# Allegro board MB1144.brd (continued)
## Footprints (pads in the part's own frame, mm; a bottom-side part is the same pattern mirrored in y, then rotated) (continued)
XTAL_SOCKET
  round 2.108 hole 1.346: 1(0,0) 2(-5.08,0)

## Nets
+1V8: C107.1 C109.1 C120.1 C123.1 TP16.1 U27.2 U27.4 U29.D1 U29.D8 U29.G9
+3V3: C61.2 C69.2 C70.2 C71.1 C78.2 C84.1 C85.1 C98.1 C101.1 C111.1 C126.1 CN2.28 CN13.7 CN19.24 CN19.25 JP1.3 JP2.1 JP10.3 LD1.1 LD2.1 LD3.1 LD4.1 R6.1 R8.1 R9.1 R14.2 R20.2 R44.1 R70.1 R112.1 R115.1 R204.1 R211.1 R212.1 R214.1 R215.1 R216.1 R217.1 R219.1 R242.1 TP17.1 U10.22 U10.26 U11.7 U12.8 U21.7 U21.18 U22.7 U22.18 U27.3 U28.4 U29.B2 U29.C2 U29.E9
+3V3_STLINK: C81.1 C86.2 C87.1 C93.2 C94.2 C95.2 C96.1 CN16.4 JP18.1 R181.2 R252.2 T4.3 U20.5 U23.1 U23.9 U23.24 U23.36 U23.48 U24.1 U25.8
+3V6: C20.1 C99.1 R207.2 TP12.1 U5.G5 U26.2 U26.4
+5V: C75.1 C116.1 C135.1 C138.1 C140.1 CN2.25 JP17.1 JP17.3 JP17.5 JP17.7 R128.1 R165.2 R169.2 R223.1 SB43.2 TP10.1 U1.5 U15.4 U26.3 U28.6 U30.6 U34.6
D5V: CN6.28 D7.1 JP17.2
GND: B1.1 B1.4 BT1.2 C1.1 C2.1 C3.2 C4.1 C5.1 C6.1 C7.1 C8.2 C9.1 C10.1 C11.2 C12.2 C13.1 C14.1 C15.2 C16.1 C17.2 C18.2 C19.2 C20.2 C21.2 C22.2 C23.1 C24.1 C25.1 C26.1 C27.2 C28.2 C29.2 C30.2 C31.2 C32.2 C33.2 C34.1 C35.1 C36.1 C37.1 C38.1 C39.1 C40.2 C41.1 C42.2 C43.1 C44.2 C45.2 C46.2 C47.1 C48.1 C49.1 C50.1 C51.1 C52.1 C53.2 C54.2 C55.2 C56.2 C57.2 C58.1 C59.2 C60.1 C61.1 C63.2 C65.2 C66.1 C67.2 C68.1 C69.1 C70.1 C71.2 C72.2 C73.2 C74.1 C75.2 C76.2 C78.1 C79.2 C80.2 C81.2 C82.2 C83.2 C84.2 C85.2 C86.1 C87.2 C88.1 C89.1 C90.2 C91.1 C92.2 C93.1 C94.1 C95.1 C96.2 C97.2 C98.2 C99.2 C100.2 C101.2 C103.2 C104.2 C107.2 C108.2 C109.2 C110.2 C111.2 C112.2 C114.2 C116.2 C117.1 C118.2 C119.2 C120.2 C121.2 C122.2 C123.2 C125.1 C126.2 C127.1 C128.1 C131.2 C132.2 C133.2 C134.2 C135.2 C137.2 C138.2 C139.2 C140.2 C141.1 C142.2 C143.1 C144.2 C145.2 CN1.5 CN1.6 CN1.7 CN1.8 CN1.9 CN1.10 CN2.2 CN2.4 CN2.6 CN2.8 CN2.10 CN2.12 CN2.16 CN2.18 CN2.20 CN2.22 CN3.7 CN4.3 CN5.3 CN5.6 CN5.10 CN5.11 CN6.1 CN6.11 CN6.22 CN6.36 CN6.39 CN7.1 CN7.15 CN7.26 CN7.39 CN8.1 CN9.5 CN9.10 CN9.11 CN12.3 CN12.5 CN12.9 CN12.11 CN12.13 CN12.15 CN12.17 CN12.19 CN13.8 CN15.4 CN15.6 CN15.8 CN15.10 CN15.12 CN15.14 CN15.16 CN15.18 CN15.20 CN16.2 CN17.4 CN17.5 CN17.6 CN18.6 CN18.9 CN19.26 CN19.27 CN19.30 CN23.5 CN23.17 D1.D2 D2.3 JP4.1 JP13.1 L2.4 L2.5 L2.6 L3.2 LD7.2 LD8.1 R19.2 R21.1 R27.2 R30.1 R45.2 R52.1 R77.1 R100.2 R101.2 R102.2 R113.2 R121.1 R124.2 R137.2 R138.2 R139.2 R155.1 R159.1 R163.1 R164.1 R168.2 R170.1 R171.2 R172.1 R174.1 R183.2 R184.2 R187.2 R191.2 R192.1 R195.2 R196.2 R202.1 R203.2 R206.2 R209.1 R213.2 R218.2 R220.2 R221.2 R224.1 R226.1 R230.1 R232.1 R234.1 R239.2 R240.2 R241.2 R243.1 R245.2 R251.1 R261.1 R267.2 RV1.2 RV1.3 RV3.3 SB7.2 SW1.3 T1.2 T6.2 TP1.1 TP3.1 TP11.1 TP18.1 U1.2 U2.D1 U2.E6 U3.7 U3.12 U3.13 U3.17 U4.7 U4.12 U4.13 U4.17 U5.E8 U5.H2 U5.H7 U6.1 U6.2 U6.3 U6.4 U7.16 U7.30 U7.31 U7.38 U7.51 U7.61 U7.71 U7.83 U7.94 U7.107 U7.120 U7.130 U7.143 U8.2 U9.4 U10.4 U10.12 U10.23 U10.25 U11.8 U12.4 U13.3 U14.8 U15.11 U16.3 U17.2 U18.2 U19.2 U20.2 U21.4 U21.10 U21.15 U21.21 U21.28 U21.34 U21.39 U21.45 U21.48 U22.4 U22.10 U22.15 U22.21 U22.28 U22.34 U22.39 U22.45 U23.8 U23.23 U23.35 U23.47 U24.4 U24.5 U25.4 U27.1 U28.2 U28.7 U29.A1 U29.A3 U29.A4 U29.A5 U29.C1 U29.D6 U29.E2 U29.E7 U29.E8 U29.F7 U29.G5 U29.H9 U30.2 U30.4 U30.14 U30.22 U32.3 U32.10 U33.9 U33.25 U34.2 U34.7 U35.5 U36.2 U36.5 U37.4
VDD: B2.1 B2.4 C12.1 C18.1 C19.1 C21.1 C22.1 C31.1 C39.2 C40.1 C44.1 C49.2 C66.2 C72.1 C74.2 C76.1 C79.1 C83.1 C90.1 C92.1 C97.1 C112.1 C118.1 C119.1 C121.1 C132.1 C134.1 CN3.5 CN7.40 CN12.1 CN15.1 CN15.2 CN18.4 JP2.2 JP11.1 JP12.1 JP16.3 R22.1 R25.1 R28.1 R29.1 R32.1 R41.1 R42.1 R46.2 R51.2 R57.2 R60.2 R74.1 R96.2 R114.2 R117.2 R120.2 R126.2 R127.1 R133.1 R135.2 R152.2 R153.2 R157.2 R160.2 R161.1 R166.1 R175.1 R176.1 R178.1 R182.1 R185.1 R186.1 R190.1 R193.1 R197.1 R200.2 R229.1 R231.1 R233.1 R237.1 R246.1 R247.2 R248.2 R249.2 R250.2 R263.1 R264.1 RV3.1 SW1.1 T3.4 TP5.1 U2.A6 U2.D6 U2.E1 U3.1 U4.1 U5.D8 U5.F1 U6.8 U8.3 U9.8 U12.1 U12.5 U13.5 U14.16 U15.5 U16.5 U21.1 U21.24 U21.25 U21.31 U21.42 U22.31 U22.42 U24.8 U25.1 U25.5 U29.D2 U30.21 U32.6 U32.14 U33.21
VDD_ADJ: C131.1 C133.1 JP2.3 R236.1 TP13.1 U34.4
VDD_IO: C35.2 C46.1 JP3.2 TP4.1 U7.95 U7.131
VDD_MCU: C32.1 C38.2 C41.2 C42.1 C43.2 C45.1 C48.2 C50.2 C51.2 JP1.1 JP3.1 JP10.1 JP11.2 JP11.3 U7.17 U7.39 U7.52 U7.62 U7.72 U7.84 U7.108 U7.121 U7.144
VDD_USB: C33.1 C36.2 JP1.2 TP2.1 U7.106
VDDA: C59.1 C60.2 CN10.2 L1.2 TP8.1 U7.33
A0: CN6.25 U2.A3 U5.E2 U7.10 U21.47
A0_1DELAY: SB44.1 U21.2 U21.40
A0_2DELAY: SB45.1 U21.9
A1: CN6.26 SB51.1 U2.A4 U5.D2 U7.11 U21.37
A1_1DELAY: SB50.1 U21.12
A1_BUF: R166.2 SB50.2 SB51.2 U22.1 U22.24
A2: CN6.32 U2.A5 U5.C2 U7.12
A3: CN6.34 U2.B3 U5.A2 U7.13
A4: CN6.37 U2.B4 U5.B2 U7.14
A5: CN6.38 U2.C3 U5.D3 U7.15
A6: CN7.17 U2.C4 U5.C3 U7.50
A7: CN7.18 U2.D4 U5.A3 U7.53
A8: CN7.16 U2.H2 U5.B6 U7.54
A9: CN7.14 U2.H3 U5.A6 U7.55
A10: CN7.12 U2.H4 U5.C6 U7.56
A11: CN7.11 U2.H5 U5.D6 U7.57
A12: CN6.13 U2.G3 U5.B7 U7.87
A13: CN6.12 U2.G4 U5.A7 U7.88
A14: CN6.14 U2.F3 U5.C7 U7.89
A15: CN6.10 U2.F4 U5.D7 U7.90
A16: CN14.30 U2.E4 U5.E7
A17: R151.1 U2.D3 U5.B3
A18: CN14.34 U2.H1 U5.C4
A19: R139.1 R150.1 U2.G2 U5.D5
A20: R84.1 R100.1 U2.H6 U5.D4
A21: R85.1 R101.1 U2.E3 U5.C5
A22: R86.1 R102.1 U5.B8
A23: R138.1 R149.1 U5.C8
AIN_1: R183.1 R186.2 U23.10
BL_VDD: C113.2 C115.1 CN19.28 L4.1 R259.1
BOOT0: CN7.20 JP8.1 R67.1 U7.138
COMP2_INP: CN11.44 JP7.3
COMP2_OUT: CN11.14 TP6.1
D0: CN14.36 U2.B6 U5.E3 U22.26
D1: CN14.38 U2.C5 U5.H3 U22.27
D2: CN6.17 U2.C6 U5.E4 U7.114 U22.29
D3: CN6.16 U2.D5 U5.H4 U7.115 U22.30
D4: CN7.10 U2.E5 U5.H5 U7.58 U22.32
D5: CN7.9 U2.F5 U5.E5 U7.59 U22.33
D6: CN7.8 U2.F6 U5.H6 U7.60 U22.35
D7: CN7.7 U2.G6 U5.E6 U7.63 U22.36
D8: CN7.6 U2.B1 U5.F3 U7.64 U22.37
D9: CN7.5 U2.C1 U5.G3 U7.65 U22.38
D10: CN7.4 U2.C2 U5.F4 U7.66 U22.40
D11: CN7.3 U2.D2 U5.G4 U7.67 U22.41
D12: CN7.2 U2.E2 U5.F5 U7.68 U22.43
D13: CN14.24 U2.F2 U5.G6 U22.44
D14: CN14.26 U2.F1 U5.F6 U22.46
D15: CN14.28 U2.G1 U5.G7 U22.47
E5V: C100.1 D5.1 JP17.8 L2.3
I2C_SCL: CN3.3 R60.1 R61.1 U29.H1 U32.4 U33.19
I2C_SDA: CN3.1 R57.1 R58.1 U29.F3 U32.5 U33.20
IRDA_RX: JP15.4 U11.4
LCD_CSN: CN19.1 SB46.2 SB47.2
LCD_D0: CN19.6 U22.23
LCD_D1: CN19.7 U22.22
LCD_D2: CN19.8 U22.20
LCD_D3: CN19.9 U22.19
LCD_D4: CN19.10 U22.17
LCD_D5: CN19.11 U22.16
LCD_D6: CN19.12 U22.14
LCD_D7: CN19.13 U22.13
LCD_D8: CN19.14 U22.12
LCD_D9: CN19.15 U22.11
LCD_D10: CN19.16 U22.9
LCD_D11: CN19.17 U22.8
LCD_D12: CN19.18 U22.6
LCD_D13: CN19.19 U22.5
LCD_D14: CN19.20 U22.3
LCD_D15: CN19.21 U22.2
LCD_NE3_BUF: R161.2 SB48.2 SB49.2 U22.25 U22.48
LCD_RDN: CN19.4 U21.6
LCD_RS: CN19.2 SB44.2 SB45.2
LCD_RSTN: CN19.5 U21.8
LCD_WRN: CN19.3 U21.5
LCDCOM0: CN11.3 U7.100
LCDCOM1: CN11.1 U7.101
LCDCOM2: CN11.5 U7.102
LCDCOM3: CN11.7 U7.140
LCDCOM4: CN14.7 U7.111
LCDCOM5: CN14.5 U7.112
LCDCOM6: CN14.3 U7.113
LCDCOM7: CN14.1 U7.116
LCDSEG0: CN14.47 R82.1
LCDSEG1: CN11.35 R81.1
LCDSEG2: CN11.33 R78.2
LCDSEG3: CN11.41 R68.1
LCDSEG4: CN11.39 R66.1
LCDSEG5: CN11.37 R62.1
LCDSEG6: CN11.47 R56.1
LCDSEG7: CN11.45 RS1.9 U7.133 U24.6
LCDSEG8: CN11.43 RS1.5 U7.134 U23.19
LCDSEG9: CN11.13 U7.135
LCDSEG10: CN11.11 R50.1
LCDSEG11: CN11.9 R48.1
LCDSEG12: CN11.19 R39.2
LCDSEG13: CN11.17 R38.1
LCDSEG14: CN11.15 U7.75
LCDSEG15: CN11.25 U7.76
LCDSEG16: CN11.23 U7.139
LCDSEG17: CN11.21 RS1.7 U7.110 U23.17
LCDSEG18: CN11.31 R97.1
LCDSEG19: CN11.29 R98.1
LCDSEG20: CN11.27 R99.1
LCDSEG21: CN14.9 U7.137
LCDSEG22: CN14.11 R65.1
LCDSEG23: CN14.13 R64.1
LCDSEG24: CN14.15 R36.1
LCDSEG25: CN14.17 R33.1
LCDSEG26: CN14.19 SB28.2 U7.98
LCDSEG27: CN14.21 SB29.2 U7.99
LCDSEG28: CN14.23 U7.77
LCDSEG29: CN14.25 U7.78
LCDSEG30: CN14.27 U7.79
LCDSEG31: CN14.29 U7.80
LCDSEG32: CN14.31 U7.81
LCDSEG33: CN14.33 U7.82
LCDSEG34: CN14.35 U7.85
LCDSEG35: CN14.37 U7.86
LCDSEG36: CN14.39 U7.141
LCDSEG37: CN14.41 U7.142
LCDSEG38: CN14.43 R103.2
LCDSEG39: CN14.45 R104.2
LED_STLINK: R253.1 R254.1 U23.30
MCO: U23.29
MICROAB_N: CN1.2 D1.D1 R3.1
MICROAB_P: CN1.3 D1.C1 R4.1
NE3_1DELAY: SB46.1 SB48.1 U21.3 U21.38
NE3_2DELAY: SB47.1 U21.11
NETB2_2: B2.2 B2.3 R244.1 R245.1
NETB3_1: B3.1 R248.1 U33.3
NETB3_2: B3.2 R246.2 U33.1
NETB3_3: B3.3 R247.1 U33.2
NETB3_4: B3.4 R249.1 U33.4
NETB3_5: B3.5 R251.2
NETB3_6: B3.6 R250.1 U33.5
NETBT1_1: BT1.1 JP12.3
NETC1_2: C1.2 CN2.33 SB32.1
NETC2_2: C2.2 CN2.34 SB31.1
NETC3_1: C3.1 R7.2 SB17.1
NETC4_2: C4.2 CN2.31 SB1.2 SB35.1
NETC5_2: C5.2 CN2.30 R20.1 SB3.1
NETC6_2: C6.2 R12.2 SB20.1
NETC7_2: C7.2 CN2.1 R14.1 SB29.1
NETC8_1: C8.1 SB1.1
NETC9_2: C9.2 CN2.29 SB37.2
NETC10_2: C10.2 R17.1 SB42.1
NETC11_1: C11.1 R13.2 R19.1 SB16.1
NETC13_2: C13.2 R10.1 SB36.1
NETC14_2: C14.2 R11.1 SB34.1
NETC15_1: C15.1 CN1.1 CN11.2 D1.B3 R1.1 R2.2 R108.2 U1.1
NETC16_2: C16.2 R15.1 SB25.2
NETC17_1: C17.1 R16.2 SB22.1
NETC23_2: C23.2 C28.1 U4.2 U4.3 U4.9
NETC24_2: C24.2 C27.1 U3.2 U3.3 U3.9
NETC25_2: C25.2 U4.4
NETC26_2: C26.2 U3.4
NETC29_1: C29.1 CN4.2 R26.2 R27.1 U3.5 U3.8
NETC30_1: C30.1 R28.2 U5.B5
NETC34_2: C34.2 SB4.1
NETC37_2: C37.2 SB6.1
NETC47_2: C47.2 R72.1 R73.2
NETC52_2: C52.2 C53.1 R92.2 U7.32
NETC55_1: C55.1 R95.2 X2.1
NETC56_1: C56.1 R87.1 X1.2
NETC57_1: C57.1 R88.1 X1.1
NETC62_1: C62.1 U10.24
NETC62_2: C62.2 U10.28
NETC63_1: C63.1 U10.3
NETC64_1: C64.1 U10.1
NETC64_2: C64.2 U10.2
NETC65_1: C65.1 U10.27
NETC67_1: C67.1 C68.2 R115.2 U11.6
NETC73_1: C73.1 R69.2 R122.2
NETC77_1: C77.1 U14.9
NETC77_2: C77.2 R130.2 R134.2
NETC80_1: C80.1 D5.2 D6.2 D7.2 D8.2 U20.1 U20.3
NETC82_1: C82.1 U20.4
NETC102_1: C102.1 U29.H8
NETC102_2: C102.2 U29.G8
NETC103_1: C103.1 U29.G7
NETC104_1: C104.1 U29.H7
NETC105_1: C105.1 CN20.4 U29.G6
NETC105_2: C105.2 R195.1
NETC106_1: C106.1 CN20.6 U29.H6
NETC106_2: C106.2 R196.1
NETC108_1: C108.1 U29.E6
NETC110_1: C110.1 U29.F1
NETC113_1: C113.1 C115.2 CN19.22 L3.1
NETC114_1: C114.1 R207.1 R209.2 U26.1
NETC117_2: C117.2 CN23.1 U30.17
NETC122_1: C122.1 U29.D9
NETC124_1: C124.1 L2.1 U31.3 Z1.2
NETC124_2: C124.2 CN22.2 CN22.3 L2.2 U31.2 Z1.1
NETC125_2: C125.2 U29.C9
NETC127_2: C127.2 JP16.1 U29.A7
NETC128_2: C128.2 U29.B6
NETC129_1: C129.1 R226.2 R227.2
NETC129_2: C129.2 U29.B3
NETC130_1: C130.1 R224.2 R225.1
NETC130_2: C130.2 U29.A2
NETC136_1: C136.1 U30.7
NETC136_2: C136.2 U30.5
NETC137_1: C137.1 U30.8
NETC139_1: C139.1 C142.1 JP16.2 R238.2 U35.1 U36.1
NETC144_1: C144.1 R124.1 R128.2 U15.3
NETCN1_4: CN1.4 D1.A3 R5.1
NETCN2_3: CN2.3 SB27.1
NETCN2_5: CN2.5 SB19.1
NETCN2_7: CN2.7 SB30.1
NETCN2_9: CN2.9 SB15.1
NETCN2_11: CN2.11 SB28.1
NETCN2_13: CN2.13 SB13.1
NETCN2_14: CN2.14 R13.1
NETCN2_15: CN2.15 R11.2
NETCN2_17: CN2.17 R10.2
NETCN2_19: CN2.19 R17.2
NETCN2_21: CN2.21 SB5.2
NETCN2_23: CN2.23 SB11.1
NETCN2_24: CN2.24 R7.1
NETCN2_26: CN2.26 R16.1
NETCN2_27: CN2.27 R15.2
NETCN2_32: CN2.32 R12.1
NETCN3_4: CN3.4 U33.12
NETCN3_8: CN3.8 SB43.1
NETCN4_1: CN4.1 R26.1 U3.6
NETCN5_2: CN5.2 D2.2 JP6.2 U8.6
NETCN5_5: CN5.5 R77.2
NETCN5_7: CN5.7 D2.1 R55.1 U8.7
NETCN5_9: CN5.9 R70.2
NETCN6_2: CN6.2 R44.2
NETCN6_30: CN6.30 R80.1
NETCN7_24: CN7.24 SB33.2
NETCN7_25: CN7.25 SB41.2
NETCN7_32: CN7.32 R79.2
NETCN7_33: CN7.33 SB23.2
NETCN7_34: CN7.34 SB24.2
NETCN8_2: CN8.2 R72.2
NETCN9_2: CN9.2 U10.6
NETCN9_3: CN9.3 U10.10
NETCN9_6: CN9.6 U10.5
NETCN9_7: CN9.7 U10.9
NETCN9_8: CN9.8 U10.7
NETCN10_1: CN10.1 R92.1
NETCN11_4: CN11.4 R194.1
NETCN11_6: CN11.6 R5.2
NETCN11_8: CN11.8 R75.2
NETCN11_10: CN11.10 R265.2
NETCN11_12: CN11.12 R266.2
NETCN11_16: CN11.16 CN13.4
NETCN11_18: CN11.18 CN13.6 R108.1
NETCN11_20: CN11.20 CN23.6 R109.1
NETCN11_24: CN11.24 R76.1
NETCN11_26: CN11.26 CN13.5
NETCN11_28: CN11.28 JP14.3 U3.10 U3.11 U3.14 U4.10 U4.11 U4.14
NETCN11_30: CN11.30 R256.1
NETCN11_32: CN11.32 U29.A9 U35.4 U36.4
NETCN11_34: CN11.34 R111.2
NETCN11_38: CN11.38 R107.2
NETCN12_2: CN12.2 CN15.7 R153.1 RS1.14 U17.1
NETCN12_4: CN12.4 CN15.9 R155.2 RS1.12 U17.3
NETCN12_6: CN12.6 CN15.13 R160.1 R162.2 RS1.10 U17.4
NETCN12_8: CN12.8 CN15.5 R152.1 RS1.8 U17.5
NETCN12_10: CN12.10 CN15.15 RS1.4 U18.3
NETCN12_12: CN12.12 SB26.2 U18.4
NETCN12_14: CN12.14 R154.1 R162.1 U19.5
NETCN12_16: CN12.16 R131.1 R156.1 U19.4
NETCN12_18: CN12.18 SB38.2 U19.3
NETCN12_20: CN12.20 SB39.2 U19.1
NETCN13_1: CN13.1 JP15.6
NETCN13_2: CN13.2 U10.13 U11.3 U12.7
NETCN14_2: CN14.2 CN18.3 R178.2
NETCN14_4: CN14.4 R140.2
NETCN14_6: CN14.6 R141.2
NETCN14_8: CN14.8 R142.2
NETCN14_10: CN14.10 JP15.1 JP15.3 JP15.5 R158.1
NETCN14_12: CN14.12 R143.2
NETCN14_14: CN14.14 R144.2
NETCN14_16: CN14.16 R145.2
NETCN14_18: CN14.18 R146.2
NETCN14_20: CN14.20 R147.2
NETCN14_22: CN14.22 R148.2
NETCN14_32: CN14.32 R151.2
NETCN14_40: CN14.40 U2.A1
NETCN14_42: CN14.42 U2.B2
NETCN14_44: CN14.44 R149.2
NETCN14_46: CN14.46 R150.2
NETCN15_3: CN15.3 R126.1 R131.2 RS1.6 U18.1
NETCN15_11: CN15.11 R157.1 R159.2
NETCN15_17: CN15.17 R163.2
NETCN15_19: CN15.19 R164.2
NETCN17_2: CN17.2 R180.2
NETCN17_3: CN17.3 R177.2 R179.2
NETCN18_1: CN18.1 R142.1 R175.2
NETCN18_2: CN18.2 R141.1 R176.2
NETCN18_5: CN18.5 R140.1
NETCN18_7: CN18.7 R147.1 R182.2
NETCN18_8: CN18.8 R148.1 R185.2
NETCN18_10: CN18.10 R194.2
NETCN19_23: CN19.23 R259.2 T6.3
NETCN19_31: CN19.31 U32.16
NETCN19_32: CN19.32 U32.13
NETCN19_33: CN19.33 U32.1
NETCN19_34: CN19.34 U32.15
NETCN20_2: CN20.2 R192.2
NETCN20_3: CN20.3 R191.1
NETCN21_2: CN21.2 R221.1
NETCN21_3: CN21.3 R220.1
NETCN21_4: CN21.4 R227.1
NETCN21_6: CN21.6 R225.2
NETCN22_1: CN22.1 U31.1
NETCN23_2: CN23.2 U30.16
NETCN23_3: CN23.3 U30.15
NETCN23_4: CN23.4 U30.13
NETCN23_7: CN23.7 U30.11
NETCN23_8: CN23.8 U30.12
NETCN23_18: CN23.18 R242.2 U30.9
NETD3_1: D3.1 R59.1
NETD3_2: D3.2 JP8.2
NETD4_1: D4.1 JP9.2
NETD4_2: D4.2 R93.1 U10.16
NETJP4_2: JP4.2 R45.1 U8.8
NETJP4_3: JP4.3 R46.1
NETJP5_1: JP5.1 RV3.2
NETJP5_2: JP5.2 JP7.2
NETJP5_3: JP5.3 R51.1 R52.2
NETJP6_1: JP6.1 R55.2
NETJP7_1: JP7.1 R63.1
NETJP10_2: JP10.2 L1.1
NETJP11_4: JP11.4 R123.1 T2.1 T2.2 T2.5 T2.6 U15.12
NETJP12_2: JP12.2 U7.6
NETJP13_2: JP13.2 R133.2 U5.B4
NETJP14_1: JP14.1 U29.C6
NETJP14_2: JP14.2 U35.3 U36.3
NETJP15_2: JP15.2 U10.17
NETJP19_1: JP19.1 R145.1
NETJP19_2: JP19.2 R21.2 U1.4
NETL4_2: L4.2 R219.2 R223.2
NETLD1_2: LD1.2 R258.2
NETLD2_2: LD2.2 R257.2
NETLD3_2: LD3.2 R256.2
NETLD4_2: LD4.2 R255.2
NETLD5_1: LD5.1 R6.2
NETLD5_2: LD5.2 T1.3
NETLD6_1: LD6.1 R9.2
NETLD6_2: LD6.2 R8.2 R109.2 U1.3
NETLD7_1: LD7.1 R165.1
NETLD8_2: LD8.2 R253.2
NETLD8_3: LD8.3 R254.2
NETLD8_4: LD8.4 R252.1
NETLD9_1: LD9.1 R268.2
NETLD9_2: LD9.2 R110.2 U37.8
NETR1_2: R1.2 R261.2 T1.1
NETR18_1: R18.1 R22.2 U2.B5
NETR23_2: R23.2 U3.15
NETR24_1: R24.1 R146.1
NETR24_2: R24.2 U4.15
NETR25_2: R25.2 U5.F7
NETR29_2: R29.2 R31.1 U4.6
NETR30_2: R30.2 R31.2 U4.5 U4.8
NETR32_2: R32.2 SB10.2 U5.A4
NETR33_2: R33.2 SB4.2 SB30.2 U7.97
NETR34_1: R34.1 R119.2 R189.1
NETR35_1: R35.1 R199.2
NETR36_2: R36.2 SB2.2 SB27.2 U7.96
NETR37_1: R37.1 SB2.1
NETR38_2: R38.2 SB6.2 U7.74
NETR39_1: R39.1 R40.1 SB3.2 U7.73
NETR40_2: R40.2 TS1.1
NETR41_2: R41.2 R43.1 U5.F2
NETR42_2: R42.2 SB7.1 U6.7
NETR48_2: R48.2 SB8.2 U7.70
NETR50_2: R50.2 SB9.2 U7.69
NETR53_2: R53.2 R205.2
NETR54_2: R54.2 R258.1
NETR56_2: R56.2 SB12.2 SB13.2 U7.47
NETR59_2: R59.2 U10.20
NETR62_2: R62.2 SB14.2 SB15.2 U7.46
NETR64_2: R64.2 SB16.2 U7.45
NETR65_2: R65.2 SB17.2 U7.44
NETR66_2: R66.2 SB18.2 SB19.2 U7.43
NETR67_2: R67.2 SW1.2
NETR68_2: R68.2 SB20.2 SB21.2 U7.42
NETR71_1: R71.1 R74.2 U9.1
NETR71_2: R71.2 SB8.1
NETR75_1: R75.1 U8.1
NETR76_2: R76.2 U8.4
NETR78_1: R78.1 SB22.2 U7.37
NETR81_2: R81.2 SB31.2 U7.36
NETR82_2: R82.2 SB32.2 U7.35
NETR89_1: R89.1 R201.2
NETR90_1: R90.1 R208.2
NETR91_1: R91.1 R127.2 U14.12
NETR97_2: R97.2 SB34.2 U7.26
NETR98_2: R98.2 SB36.2 U7.27
NETR99_2: R99.2 SB42.2 U7.28
NETR103_1: R103.1 SB26.1 U7.1
NETR104_1: R104.1 R154.2 U7.2
NETR105_1: R105.1 R198.2
NETR106_1: R106.1 R222.1
NETR107_1: R107.1 U30.24
NETR112_2: R112.2 U11.1
NETR113_1: R113.1 U11.5
NETR114_1: R114.1 R116.1 U12.3
NETR117_1: R117.1 R118.1 R119.1 U12.2
NETR122_1: R122.1 U13.2
NETR123_2: R123.2 R135.1 T2.4
NETR125_1: R125.1 U15.13 U15.14
NETR125_2: R125.2 R132.1 U15.9
NETR129_1: R129.1 R136.2 U15.10
NETR129_2: R129.2 U15.1 U15.2
NETR130_1: R130.1 U14.11
NETR132_2: R132.2 U13.1 U15.8
NETR134_1: R134.1 U14.10
NETR136_1: R136.1 U15.6 U15.7
NETR137_1: R137.1 R144.1 T3.1 T3.2 T3.5 T3.6
NETR143_1: R143.1 R210.2
NETR156_2: R156.2 SB40.2
NETR167_2: R167.2 R171.1 R173.2 T4.1
NETR168_1: R168.1 U23.44
NETR172_2: R172.2 U23.2
NETR174_2: R174.2 U23.3
NETR177_1: R177.1 T4.2
NETR184_1: R184.1 U37.5
NETR187_1: R187.1 U23.20
NETR188_1: R188.1 U23.12
NETR189_2: R189.2 R190.2 U25.2
NETR193_2: R193.2 U25.3
NETR197_2: R197.2 U29.G2
NETR198_1: R198.1 U29.E4
NETR199_1: R199.1 U29.G3
NETR200_1: R200.1 U29.D4 U29.D5
NETR201_1: R201.1 U29.G1
NETR202_2: R202.2 U28.3
NETR203_1: R203.1 R204.2 U28.5
NETR205_1: R205.1 U29.F2
NETR206_1: R206.1 U28.1
NETR208_1: R208.1 U29.E3
NETR210_1: R210.1 U30.26
NETR211_2: R211.2 TP14.1 U30.28
NETR212_2: R212.2 TP15.1 U30.27
NETR213_1: R213.1 U30.23 U33.10
NETR214_2: R214.2 U30.20 U33.6
NETR215_2: R215.2 U30.19 U33.7
NETR216_2: R216.2 U30.1
NETR217_2: R217.2 R218.1 U30.18
NETR222_2: R222.2 U29.D3
NETR228_2: R228.2 R229.2 U32.2 U33.22
NETR230_2: R230.2 R231.2 U33.18
NETR232_2: R232.2 R233.2 U33.23
NETR234_2: R234.2 U34.3
NETR235_1: R235.1 R236.2 U34.5
NETR235_2: R235.2 RV1.1
NETR237_2: R237.2 R243.2 U33.24
NETR238_1: R238.1 U35.2
NETR239_1: R239.1 U32.9
NETR240_1: R240.1 U34.1
NETR241_1: R241.1 U30.3 U33.8
NETR255_1: R255.1 U32.11
NETR257_1: R257.1 U32.8
NETR260_1: R260.1 U33.11
NETR260_2: R260.2 R267.1 T6.1
NETR263_2: R263.2 R265.1 U6.5
NETR264_2: R264.2 R266.1 U6.6
NETSB9_1: SB9.1 U9.6
NETSB12_1: SB12.1 U9.5
NETSB14_1: SB14.1 U9.2
NETSB18_1: SB18.1 U9.3
NETSB21_1: SB21.1 U9.7
NETT3_3: T3.3 U13.4 U16.4
NETTP19_1: TP19.1 U23.21
NETU14_3: U14.3 U16.2
NETU23_13: U23.13 U25.7
OPAMP1_INM: CN14.48 R120.1 R121.2 RV2.1
OPAMP1_INP: R63.2 R83.2
OPAMP1_OUT: R111.1 RV2.2 RV2.3 TP9.1
OSC_IN: C88.2 U23.5 X3.2
OSC_OUT: C89.2 U23.6 X3.1
PA0: CN7.37 R83.1 SB35.2 U7.34
PA4: CN7.38 R73.1 U7.40
PA5: CN7.35 R69.1 U7.41
PA11: CN6.6 D1.D3 R3.2 U7.103
PA12: CN6.7 D1.C3 R4.2 U7.104
PA13: CN6.5 RS1.13 U7.105 U23.27 U24.7
PA14: CN6.8 RS1.11 U7.109 U23.15 U23.26
PB2: CN7.13 R54.1 SB11.2 U7.48
PB6: CN6.40 R118.2 U7.136
PC3: CN7.36 R94.1 U7.29
PC13: R80.2 R244.2 U7.7
PC14: R87.2 SB41.1 U7.8
PC15: R88.2 SB33.1 U7.9
PD3: CN6.15 R23.1 U7.117
PD4: CN6.18 U2.A2 U5.G2 U7.118 U21.43
PD5: CN6.19 U2.G5 U5.A5 U7.119 U21.44
PD6: CN6.24 R53.1 SB10.1 U7.122
PD7: CN6.23 R18.2 U7.123
PE4: CN7.21 R84.2 SB40.1 U7.3
PE5: CN7.23 R85.2 SB38.1 U7.4
PE6: CN7.22 R86.2 SB39.1 U7.5
PF6: CN7.27 R105.2 U7.18
PF7: CN7.28 R106.2 U7.19
PF8: CN7.30 R89.2 U7.20
PF9: CN7.29 R90.2 SB25.1 U7.21
PF10: CN7.31 R91.2 SB37.1 U7.22
PF11: CN7.19 CN13.3 U7.49
PG6: CN6.3 R35.2 SB5.1 U7.91
PG7: CN6.4 R34.2 U7.92
PG8: CN6.9 R158.2 R188.2 U7.93
PG9: CN6.20 R43.2 U7.124
PG10: CN6.21 SB49.1 U7.125 U21.46
PG11: CN6.27 R93.2 U7.126
PG12: CN6.31 R116.2 U7.127
PG13: CN6.29 R58.2 U7.128
PG14: CN6.33 R61.2 U7.129
PG15: CN6.35 R228.1 U7.132
PH0: C54.1 SB24.1 U7.23 X2.2
PH1: R95.1 SB23.1 U7.24
PWR_ENN: R262.1 U23.28 U37.3
PWR_EXT: JP18.2 R169.1 R170.2 U23.39
RESET#: B1.2 B1.3 C141.2 JP9.1 R79.1 R96.1 RS1.3 U7.25 U21.41 U23.18
SHUNT_X1000: T2.3 U14.2
STL_USB_DM: R180.1 U23.32
STL_USB_DP: R179.1 U23.33
STM_JTCK_SWCLK: CN16.3 U23.37
STM_JTMS_SWDIO: CN16.1 U23.34
STM_RST: C91.2 R181.1 U23.7
SWIM_PU_CTRL: U23.4
T_JTDO: U23.16 U23.31 U24.3
T_SWDIO_IN: U23.25 U24.2
TS_SHIELD: R37.2
U5V: D6.1 JP17.6 R2.1
U5V_STLINK: C143.2 JP17.4 U37.6 U37.7
USART1_RTS_3V3: U10.14 U12.6
USB_RENUMN: R173.1 U23.38
VLCD: C58.2 R94.2 TP7.1
VUSB_ST_LINK: C145.1 CN17.1 D8.1 R110.1 R167.1 R262.2 R268.1 U37.1 U37.2

Pads without a net: B3 7 8; CN3 2 6; CN5 1 4 8; CN9 1 4 9; CN11 22 36 40 42 46 48; CN12 7; CN16 5; CN18 11 12 13 14; CN19 29; CN20 5 7; CN21 5 7; D1 A2 B1 B2 C2; RS1 1 2 15 16; U3 16; U4 16; U5 A1 A8 B1 C1 D1 E1 F8 G1 G8 H1 H8; U7 145 146 147 148; U8 5; U9 9; U10 8 11 15 18 19 21; U11 2; U14 1 4 5 6 7 13 14 15; U16 1; U18 5; U21 13 14 16 17 19 20 22 23 26 27 29 30 32 33 35 36; U23 11 14 22 40 41 42 43 45 46; U25 6; U29 A6 A8 B1 B4 B5 B7 B8 B9 C3 C4 C5 C7 C8 D7 E1 E5 F4 F5 F6 F8 F9 G4 H2 H3 H4 H5; U30 10 25; U32 7 12 17; U33 13 14 15 16 17

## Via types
v1: diameter 0.508, hole 0.254, TOP to BOTTOM, 722 vias
v2: diameter 0.305, hole 0.152, TOP to BOTTOM, 10 vias
v3: diameter 0.61, hole 0.305, TOP to BOTTOM, 551 vias
v4: diameter 0.483, hole 0.254, TOP to BOTTOM, 33 vias
v5: diameter 0.406, hole 0.203, TOP to BOTTOM, 6 vias

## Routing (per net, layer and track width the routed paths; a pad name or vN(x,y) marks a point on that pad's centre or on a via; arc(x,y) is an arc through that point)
+1V8: length 40.1
  TOP w0.229: 82.27,30.99 U29.D1 ; U29.D8 v2(78.48,31.24)
  TOP w0.254: U29.G9 78.02,32.49 77.95,32.43 77.68,32.43 v1(77.55,32.3) ; v3(83.53,31.24) 82.52,31.24 82.27,30.99
  TOP w0.381: C120.1 v1(75.79,31.24) ; v3(83.53,31.24) 83.66,31.24 85.57,29.34 C123.1 ; C109.1 v1(75.53,34.04)
  TOP w0.508: v1(76.93,30.33) 76.9,30.33 75.97,29.39 75.89,29.39 75,28.5 72.69,28.5 72.21,28.02 72.21,16.26 70.58,14.63 TP16.1 ; U27.4 60.51,37.47 ; U27.4 59.43,35.64 ; U27.4 58.35,37.47 ; U27.4 59.43,39.29 ; 67.61,37.72 C107.1 ; C107.1 69.49,37.72 ; C107.1 68.55,38.53 ; C107.1 68.55,36.91 ; 65.73,36.78 U27.2 ; U27.2 66.81,37.47 ; U27.2 65.73,38.15 ; U27.2 64.65,37.47
  vias: v1(70.45,38.35) v1(70.45,37.72) v1(71.09,38.35) v1(71.09,37.72)
+3V3: length 249.7
  TOP w0.203: U29.C2 v2(81.48,30.24) U29.B2
  TOP w0.229: 77.69,31.49 U29.E9
  TOP w0.254: U22.18 79.68,64.81 v3(79.6,64.9) ; 77.26,31.55 77.32,31.49 77.69,31.49 ; U22.7 74.18,62.15 C85.1
  TOP w0.279: U12.8 19.41,94.25 C69.2 ; U21.7 55.89,61.89 C84.1 ; U21.18 v3(61.39,62.4)
  TOP w0.305: U10.22 103.42,104.07 103.35,104.14 C61.2 ; U10.26 106.09,101.47 106.32,101.24 v3(106.32,101.22)
  TOP w0.356: U10.22 106.97,104.07 107.28,103.76 107.28,101.6 106.9,101.22 v3(106.32,101.22)
  TOP w0.508: v3(32.1,59.26) 32.68,58.67 38.09,58.67 40.13,60.71 v3(49.96,60.71) ; v3(70.28,65.51) 69.16,65.51 66.05,62.4 v3(61.39,62.4) ; v3(84.42,27.43) 85.06,26.8 C126.1 ; 44.29,38.68 C98.1 ; C98.1 43.54,39.5 ; C98.1 44.29,40.31 ; R20.2 51.78,159.77 v3(52.17,160.15) ; v3(74.14,32.08) 74.19,32.08 74.64,32.54 C111.1 75.69,32.77 76.9,31.55 77.26,31.55 ; 42.44,36.7 R204.1 ; R204.1 43.61,36.7 ; R204.1 43.02,37.28 ; C101.1 44.55,38.43 ; C101.1 44.09,37.97 ; C101.1 44.55,37.52 ; 64.65,39.76 U27.3 ; U27.3 66.81,39.76 ; U27.3 65.73,39.08 ; U27.3 65.73,40.45 ; v3(54.96,61.21) 55.47,61.21 C84.1 ; v3(9.49,90.98) 9.87,91.36 C71.1 ; v3(66.01,15.24) 66.14,15.24 TP17.1 ; v3(8.35,88.77) 3.52,88.77 2.89,88.14 C78.2 2.76,87.38 CN13.7 ; R9.1 22.7,161.42 22.45,161.67 v3(22.19,161.67) 21.81,161.67 21.56,161.42 R8.1 ; LD4.1 LD3.1 LD2.1 LD1.1 27.68,4.32 28.77,3.23 34.59,3.23 37.89,6.53 60.83,6.53 62.22,7.92 62.22,13.44 v3(63.95,15.16) ; R242.1 65.25,15.49 v3(64.87,15.11) ; R212.1 v3(55.34,32.38) R211.1 ; C85.1 74.52,62.1 75.15,61.47 v3(75.15,61.34) ; v3(14.45,120.78) 15.21,120.02 R70.1 ; 44.1,36.13 U28.4 44.63,36.54 ; C61.2 100.68,104.14 JP10.3 ; R216.1 v3(66.77,33.27) ; U11.7 4.58,93.6 6.32,93.6 C70.2 6.45,93.19 7.23,92.41 v3(8.17,92.41) ; v3(93.06,162.43) R14.2 ; R112.1 v3(8.73,99.31) ; R219.1 91.41,28.96 v3(91.41,28.83) ; R214.1 v3(64.74,33.27) ; R215.1 v3(65.75,33.27) ; R115.1 v3(8.22,96.14) ; v3(33.47,149.83) 33.47,149.73 34.87,148.34 37.18,148.34 37.99,147.52 37.99,139.12 R44.1 ; C69.2 v3(19.15,93.09) ; R6.1 v3(25.37,163.96) ; R217.1 v3(67.79,33.27)
  BOTTOM w0.508: v3(70.28,65.51) 72.16,63.63 72.87,63.63 v3(75.15,61.34) 76.04,61.34 v3(79.6,64.9) 81.12,66.42 85.57,66.42 92.3,73.15 100.43,73.15 102.84,75.56 102.84,87.76 104.62,89.53 104.62,97.16 106.27,98.81 106.27,101.17 v3(106.32,101.22) ; v3(49.96,60.71) 54.15,60.71 54.65,61.21 v3(54.96,61.21) 55.59,61.21 55.98,60.83 59.82,60.83 v3(61.39,62.4)
  vias: v3(42.89,41.27) v3(43.66,41.27) v3(44.42,41.27) v3(67.23,40.39) v3(67.2,39.6) v3(67.99,40.39)
+3V3_STLINK: length 173.9
  TOP w0.254: U23.24 68.12,45.51 68.8,44.83 C94.2 ; C93.2 58.9,48.01 60.19,49.3 U23.9 ; C95.2 71.61,43.8 U24.1 ; C87.1 70.66,53.47 70.49,53.3 U23.36 ; U23.48 62.62,56.34 C86.2 ; C96.1 66.66,43.17 U25.8 ; v3(60.17,53.98) 60.17,53.72 60.59,53.3 U23.1
  TOP w0.508: 17.62,10.03 21.56,13.97 25.5,13.97 28.8,17.27 34.51,17.27 39.59,22.35 39.59,28.07 40.99,29.46 50.13,29.46 52.67,32 52.67,38.23 v3(57.12,42.67) ; v3(66.9,43.81) 66.9,43.18 C96.1 ; v3(70.33,43.43) 70.58,43.69 C95.2 ; v3(24.99,74.24) 25.37,73.86 25.37,73.21 ; C81.1 25.37,73.21 ; 25.37,73.21 U20.5 ; T4.3 110.2,54.91 v3(110.2,56.26) ; v3(58.26,47.32) 58.26,47.37 58.77,47.88 C93.2 ; C86.2 v3(62.58,57.28) ; v3(40.23,56.77) 40.35,56.77 41.62,58.04 57.88,58.04 v3(58.01,57.91) ; C94.2 68.8,43.94 v3(68.68,43.81) ; 57.75,49.02 v3(56.86,49.02) ; v3(72.26,53.29) 72.08,53.47 C87.1
  BOTTOM w0.508: v3(40.23,56.77) 39.97,57.02 39.97,62.48 34.51,67.94 29.81,67.94 24.99,72.77 v3(24.99,74.24) ; v3(58.26,47.32) 58.26,45.67 57.22,44.63 57.22,42.77 v3(57.12,42.67) ; CN16.4 77.31,52.58 81.38,52.58 82.39,53.59 107.66,53.59 110.2,56.13 v3(110.2,56.26) JP18.1
+3V6: length 287.4
  TOP w0.305: U5.G5 104.47,147.06 v4(104.91,146.62)
  TOP w0.508: v3(20.03,115.95) 20.03,116.2 21.61,117.78 21.61,128.32 20.29,129.64 20.29,130.81 20.82,131.34 20.82,135.13 21.3,135.61 21.3,140.73 29.69,149.11 29.69,158.37 41.42,170.1 66.47,170.1 67.31,170.94 99.94,170.94 106.52,164.36 106.52,155.8 107.44,154.89 107.44,153.77 C20.1 107.54,152.15 108.43,151.26 108.43,149.73 v1(108.3,149.61) ; 36.75,40.51 C99.1 ; C99.1 37.69,41.33 ; C99.1 37.69,39.7 ; C99.1 38.63,40.51 ; v3(24.1,44.96) 28.67,44.96 30.58,43.05 ; U26.2 33.29,35.46 ; U26.2 31.92,35.46 ; U26.2 32.61,36.54 ; U26.2 32.61,34.38 ; U26.4 32.61,42.84 ; U26.4 34.44,41.76 ; U26.4 30.78,41.76 ; U26.4 32.61,40.68 ; R207.2 32.86,33.78 32.99,33.91
  BOTTOM w0.508: v3(20.03,115.95) 20.03,115.7 18.26,113.92 18.26,112.27 12.8,106.81 12.8,91.19 18,85.98 18,77.22 17.49,76.71 17.49,71.88 19.75,69.62 19.75,62.64 24.81,57.58 24.81,48.21 24.1,47.5 v3(24.1,44.96) ; v4(104.91,146.62) 104.87,146.66 104.87,149.22 105.51,149.86 106.34,149.86 106.6,149.61 v1(108.3,149.61) ; TP12.1 31.34,14.48 39.21,22.35 v3(39.21,39.88) v3(39.21,40.77) v3(39.21,41.66)
+5V: length 263.6
  TOP w0.305: C75.1 42.26,88.65 U15.4
  TOP w0.508: 45.65,16.3 U34.6 45.12,16.7 ; 43.15,31.19 C116.1 ; C116.1 42.33,32.13 ; C116.1 43.15,33.07 ; C116.1 43.96,32.13 ; v3(112.34,153.29) 112.24,153.39 112.24,153.8 111.27,154.76 109.09,154.76 107.92,155.93 107.92,165.91 102.08,171.75 66.9,171.75 66.08,170.94 v3(63.95,170.94) ; TP10.1 R165.2 JP17.1 ; 34.22,35.46 U26.3 ; U26.3 34.91,36.54 ; U26.3 35.59,35.46 ; U26.3 34.91,34.38 ; U1.5 23.26,157.43 v3(23.26,158.6) ; v3(60.8,11.56) 60.67,11.68 C138.1 C135.1 60.8,17.27 U30.6 ; 43.22,14.48 C140.1 ; C140.1 44.04,13.54 ; C140.1 44.04,15.42 ; C140.1 44.85,14.48 ; v3(48.96,48.06) 48.84,48.18 v3(39.21,48.18) ; C75.1 41.93,88.39 40.78,87.38 R128.1 39.97,87.38 38.83,88.52 32.35,88.52 29.94,86.11 v3(13.3,86.11) ; 65.88,56.39 65.88,57.28 65.12,58.04 59.61,58.04 v3(59.48,57.91) ; 44.1,34.23 U28.6 44.63,33.82 ; R223.1 v3(92.04,26.67)
  BOTTOM w0.508: v3(92.04,26.67) 91.66,26.29 91.66,14.73 88.49,11.56 v3(60.8,11.56) 42.89,11.56 v3(42.77,11.68) ; v3(6.06,89.66) 6.06,88.98 8.93,86.11 v3(13.3,86.11) ; v3(34.51,33.91) 34.51,43.48 v3(39.21,48.18) ; v3(48.96,48.06) 48.96,58.17 50.16,59.36 58.29,59.36 59.48,58.17 v3(59.48,57.91) ; v3(63.95,170.94) 63.47,170.46 CN2.25 ; JP17.1 JP17.3 JP17.5 JP17.7 ; SB43.2 v3(112.34,153.29)
  vias: v3(34.51,33.15) v3(35.4,33.91) v3(35.4,33.15) v3(40.86,32.64) v3(40.86,31.75) v3(41.62,32.64) v3(41.62,31.75) v3(42.01,14.99) v3(42.01,13.97) v3(42.01,11.68)
D5V: length 89.6
  TOP w0.508: v3(16.48,112.9) 16.48,112.27 19.53,109.22 29.31,109.22 v3(30.32,110.24) ; v3(35.27,117.22) 33.5,119 33.5,119.63 32.99,120.14 CN6.28 ; D7.1 14.75,70.41 v3(14.7,70.36) 12.16,67.82 10.38,67.82 9.75,67.18 9.75,64.77 JP17.2
  BOTTOM w0.508: v3(35.27,117.22) 35.27,116.97 31.21,112.9 31.21,112.01 30.32,111.12 v3(30.32,110.24) ; v3(16.48,112.9) 11.27,107.7 11.27,90.68 16.48,85.47 16.48,78.11 14.7,76.33 v3(14.7,70.36)
GND: length 773.2
  TOP w0.203: U29.E8 v2(78.98,31.24) U29.E7
  TOP w0.229: U29.E2 v2(81.48,31.24) ; v3(79.98,28.83) 79.98,29.24 U29.A5 ; v3(82.79,28.91) 82.23,29.46 U29.A1 ; U29.A3 81.23,29.07 v3(80.99,28.83) 80.99,28.83 80.73,29.09 U29.A4 ; U29.D6 v2(79.48,30.74) ; U29.C1 82.43,30.49 82.83,30.09 v3(82.91,30.09) ; v2(79.48,32.24) U29.F7 ; v2(79.98,32.74) U29.G5
  TOP w0.254: v3(10.38,152.91) 10.09,152.61 U3.12 ; v3(62.58,118.87) 62.25,118.54 U7.16 ; U7.51 74.33,126.62 C45.2 ; U7.30 69.25,116.65 v3(69.56,116.33) 69.75,116.52 U7.31 ; v3(81.25,69.98) 81.18,70.05 U22.28 ; C92.2 72.87,49.02 73.11,48.78 U24.5 ; U23.8 v3(62.33,49.8) ; U7.94 61.75,140.17 v3(62.02,140.44) ; U7.130 v3(51.28,126.65) ; v3(28.92,165.23) 29.05,165.35 D1.D2 ; C95.1 72.74,43.81 73.11,44.18 U24.4 ; v3(54.96,140.59) 54.96,140.34 55.25,140.04 U7.107 ; U23.23 67.62,47.04 v3(68,47.42) ; v3(63.46,42.06) 63.46,42.05 63.08,41.67 U25.4 ; U22.21 81.18,64.84 v3(81.12,64.9) ; U7.83 67.25,140.43 v3(67.41,140.59) ; U22.15 v3(78.18,64.88) ; v3(77.56,33.39) 77.57,33.39 77.82,33.15 78.08,33.15 U29.H9 ; U7.143 51.02,120.15 v3(50.9,120.27) ; U23.35 v3(68.29,52.8) ; U22.39 v3(75.68,70) ; v3(24.02,96.52) 24.02,96.18 23.59,95.75 U12.4 ; v3(21.05,148.84) 20.99,148.9 U4.7 ; U22.10 v3(75.68,64.88) ; U21.15 59.91,63.63 v3(59.91,62.18) ; v3(9.11,154.43) 8.86,154.43 8.44,154.01 U3.13 ; v3(77.95,69.98) 78.18,70.21 U22.34 ; U22.45 72.68,72.19 72.23,72.64 v1(72.23,72.77) ; U4.13 21.64,154.26 v3(21.81,154.43) ; U22.4 72.68,64.83 v3(72.61,64.9) ; U4.12 v3(23.55,152.61) ; v3(7.72,148.84) 7.79,148.92 U3.7
  TOP w0.279: U21.45 54.39,70.3 53.82,69.72 v3(53.82,69.47) ; U21.48 52.89,70.83 v3(52.29,70.23) ; U21.10 57.37,63.63 57.37,62.23 56.86,61.72 C84.2 ; v3(60.01,69.72) 60.01,69.75 59.89,69.87 U21.34 ; v3(73.04,136.35) 73.35,136.65 74.3,136.65 U7.71 ; U32.10 89.38,16.9 R239.2 ; v3(89.25,22.1) 89.38,21.97 U32.3 ; v5(85.01,150.19) 85.01,150.22 85.19,150.4 U2.D1 ; v3(54.12,62.33) 54.38,62.59 54.38,63.63 U21.4 ; U23.47 v3(63.12,53.63) ; v3(81.63,19.56) 82.65,19.56 82.9,19.31 U33.9 ; U7.61 73.07,131.65 v3(72.99,131.57) ; v4(85.95,155.19) 85.95,154.54 U2.E6 ; U5.E8 102.45,150.67 102.44,150.67 v4(102.44,150.75) ; v3(72.74,120.4) 73.12,120.4 73.37,120.15 U7.38 ; U21.28 v3(62.89,69.76) ; v3(63.09,65.02) 62.89,64.83 U21.21 ; v3(57.4,69.8) 57.46,69.86 57.46,70.18 57.39,70.25 U21.39 ; U7.51 v3(73.02,126.65)
  TOP w0.305: C63.2 113.32,102.71 112.73,102.12 U10.4 ; v4(106.04,149.17) 105.96,149.1 105.49,149.1 U5.H7 ; v4(106.5,143.5) 106.28,143.5 105.72,144.06 U5.H2 ; v3(110.41,107.32) U10.12 ; U7.120 53.77,131.65 54.03,131.91 v3(54.03,131.92) ; U6.1 113.8,139.02 114.01,138.81 v3(114.01,138.68) 114.01,138.63 113.76,138.37 U6.2 ; U6.3 113.7,137.72 v3(114.01,137.41) 113.67,137.07 U6.4 ; U15.11 v3(48.36,88.65) ; U10.23 v3(106.23,103.42) ; U10.25 106.33,102.12 v3(106.34,102.11)
  TOP w0.356: U16.3 v3(70.06,87.77) ; v3(72.49,87.07) 72.49,87.06 72.79,86.75 U14.8 ; U13.3 68.3,91.45 67.86,91.9 v3(67.86,91.92)
  TOP w0.381: CN1.5 v3(31.44,167.39)
  TOP w0.457: U18.2 111.22,84.2 111.35,84.33 v3(111.35,84.45) ; U28.2 v3(46.07,35.18) ; U34.2 v3(47.09,17.65) ; U19.2 v3(111.22,73.91)
  TOP w0.508: C67.2 v3(13.94,95.12) ; C67.2 12.67,96.14 ; C67.2 12.67,94.11 ; C67.2 11.78,95.12 ; CN9.5 116.81,118.31 ; CN9.5 118.08,117.17 ; CN9.5 115.54,117.17 ; CN9.5 116.81,116.03 ; C92.2 73.5,49.66 v3(73.63,49.53) ; v3(78.07,40.26) 78.84,40.26 R195.2 ; LD7.2 v3(17.88,68.02) ; LD7.2 17.21,66.42 ; LD7.2 18.54,66.42 ; U30.2 v3(55.72,17.53) ; v3(102.58,101.22) 102.58,101.09 102.71,100.97 C65.2 ; 123.19,82.8 CN15.6 ; CN15.6 124.21,83.82 ; CN15.6 123.19,84.84 ; v3(24.29,168.46) 24.61,168.46 ; v3(24.29,168.46) T1.2 ; v3(24.29,168.46) 24.29,168.66 ; v3(24.29,168.46) 24.29,168.15 ; R174.1 57.25,54.31 ; R174.1 v3(55.98,53.72) ; R174.1 57.25,53.14 ; C22.2 v3(1.24,152.65) ; C22.2 2.25,151.99 ; C22.2 2.25,153.31 ; CN9.10 118.21,126.7 ; CN9.10 118.21,121.61 ; CN9.10 119.6,124.16 ; CN9.10 116.81,124.16 ; U9.4 113.28,118.15 ; U9.4 112.74,117.6 112.31,117.17 v3(112.31,117.02) ; U9.4 112.21,118.15 ; v3(1.49,13.46) 1.49,13.72 ; v3(1.49,13.46) 1.49,13.21 ; v3(1.49,13.46) 1.75,13.46 ; v3(1.49,13.46) 1.24,13.46 ; R27.2 v3(8.35,146.3) ; C87.2 71.98,54.48 v3(72.31,54.15) ; v3(5.81,92.46) 5.58,92.69 U11.8 ; 25.99,170.23 CN1.9 ; CN1.9 25.04,171.44 ; CN1.9 26.95,171.44 ; C70.1 v3(8.3,93.47) ; CN5.3 11.43,125.09 ; CN5.3 10.16,126.24 ; CN5.3 8.89,125.09 ; CN5.3 10.16,123.95 ; CN15.18 124.21,68.58 ; CN15.18 123.19,67.56 ; CN15.18 123.19,69.6 ; T1.2 23.04,169.03 ; T1.2 22.21,168.46 ; T1.2 23.04,167.89 ; CN7.39 96.06,112.52 v3(96.67,111.91) ; CN15.20 124.21,66.04 ; CN15.20 123.19,65.02 ; CN15.20 123.19,67.06 ; v3(115.74,87.38) 115.79,87.33 U17.2 ; C134.2 v3(85.69,19.18) ; 13.75,125.14 D2.3 ; D2.3 14.32,125.96 ; D2.3 14.89,125.14 ; D2.3 v3(14.32,123.95) ; 116.81,99.11 CN9.11 ; CN9.11 118.21,101.65 ; CN9.11 118.21,96.57 ; CN9.11 119.6,99.11 ; R138.2 v3(89.76,82.68) ; v3(125.95,13.97) 126.21,13.97 ; v3(125.95,13.97) 125.95,13.72 ; v3(125.95,13.97) 125.7,13.97 ; v3(125.95,13.97) 125.95,14.22 ; v3(114.19,76.35) 115.13,76.35 R159.1 ; C138.2 v3(62.2,14.86) ; 125.95,62.99 v3(125.95,63.25) ; v3(125.95,63.25) 126.21,63.25 ; v3(125.95,63.25) 125.95,63.5 ; v3(125.95,63.25) 125.7,63.25 ; 15.59,151.38 v3(14.7,151.38) ; 15.59,151.38 15.59,152.04 ; 15.59,151.38 15.59,150.72 ; C81.2 v3(25.37,70.61) ; 27.87,169.31 CN1.6 27.08,168.26 ; 98.72,28.68 CN19.27 ; CN19.27 98.72,30.51 ; CN19.27 97.81,29.6 ; CN19.27 99.64,29.6 ; L2.5 1.99,35.41 ; L2.5 3.23,34.16 ; L2.5 1.99,32.92 ; 57.75,50.04 57.63,49.91 v3(56.74,49.91) ; CN1.10 v3(30.14,169.75) ; v3(66.34,107.44) 66.26,107.52 C55.2 ; 56.48,108.76 R102.2 ; R102.2 56.03,109.22 ; R102.2 56.36,109.09 56.36,108.84 55.98,108.46 v3(55.85,108.46) ; v3(51.91,161.67) 51.91,161.04 C5.1 ; R221.2 122.27,29.36 ; R221.2 v3(121.25,28.7) ; R221.2 122.27,28.04 ; C128.1 v3(78.2,25.53) ; C128.1 78.96,24.07 ; C128.1 78.3,24.77 ; U37.4 v3(79.09,43.81) ; C13.1 v3(79.47,158.37) ; 6.1,129.26 CN5.6 ; CN5.6 7.37,130.4 ; CN5.6 7.37,128.12 ; CN5.6 8.64,129.26 ; 64.65,35.17 U27.1 ; U27.1 65.73,35.85 ; U27.1 66.81,35.17 ; U27.1 65.73,34.48 ; C131.2 47.84,21.97 ; C131.2 47.09,22.78 ; C131.2 47.09,21.16 ; v3(88.61,27.43) 88.61,27.18 88.23,26.8 R224.1 ; R213.2 v3(60.67,33.4) ; v3(70.25,89.89) 71.32,89.89 C73.2 ; C2.1 v3(43.02,165.86) ; 55.21,108.76 R101.2 ; R101.2 R100.2 53.94,108.71 v3(54.32,108.33) ; R101.2 55.67,109.22 ; v3(45.43,126.49) 45.94,125.98 C46.2 ; CN17.5 121.48,46.08 ; CN17.5 119.63,47.92 ; CN17.5 119.63,44.23 ; CN17.5 117.79,46.08 ; C111.2 v3(72.74,32.77) ; C114.2 v3(29.81,31.11) ; 68.55,34.92 69.49,34.92 ; 68.55,34.92 68.55,35.74 ; 68.55,34.92 68.55,34.11 ; 68.55,34.92 67.61,34.92 ; R30.1 19.6,146.56 ; R30.1 18.18,146.56 ; R30.1 18.89,145.85 ; C100.2 26.31,38.99 ; C100.2 23.59,37.29 ; C100.2 23.59,40.69 ; CN12.19 v3(101.44,76.07) ; R45.2 16.1,137.69 ; R45.2 16.1,136.63 ; R45.2 v3(15.21,137.16) ; v3(94.58,162.43) C7.1 ; 77.44,24.07 C127.1 ; C127.1 v3(76.42,24.77) ; C127.1 78.1,24.77 ; CN12.11 v3(101.44,81.15) ; v3(54.96,61.95) 54.68,61.95 54.32,61.59 C83.2 ; C14.1 v3(83.28,160.15) ; 11.65,148.84 v3(11.65,149.1) ; v3(11.65,149.1) 11.65,149.35 ; v3(11.65,149.1) C27.2 ; v3(11.65,149.1) 11.91,149.1 ; C116.2 45.94,33.07 ; C116.2 46.76,32.13 ; C116.2 45.94,31.19 ; C116.2 45.13,32.13 ; CN6.1 27.4,136.65 v3(28.29,137.54) ; 10.1,149.1 C27.2 ; C27.2 10.76,148.4 ; R239.2 v3(89.38,16.13) ; 46.7,19.86 C133.2 ; C133.2 47.16,20.32 ; C133.2 46.7,20.78 ; CN5.11 8.76,140.16 ; CN5.11 7.37,137.62 ; CN5.11 10.16,137.62 ; CN5.11 8.76,135.08 ; 57.94,4.25 B1.4 ; B1.4 57.94,5.78 ; B1.4 58.95,5.02 ; B1.4 v3(56.67,5.02) ; v3(57.88,61.52) 56.94,61.52 C84.2 ; CN19.26 102.18,32.14 ; CN19.26 101.26,31.22 ; CN19.26 100.35,32.14 ; C140.2 46.83,15.42 ; C140.2 46.02,14.48 ; C140.2 47.64,14.48 ; C140.2 46.83,13.54 ; C4.1 v3(46.58,162.05) ; C47.1 89,117.98 v3(88.87,117.86) ; v3(116.05,103.25) 115.54,102.74 C63.2 ; CN15.12 123.19,77.22 ; CN15.12 124.21,76.2 ; CN15.12 123.19,75.18 ; 8.76,110.03 CN5.10 ; CN5.10 7.37,112.57 ; CN5.10 10.16,112.57 ; CN5.10 8.76,115.11 ; C76.2 v3(64.48,87.5) ; C16.1 v3(52.42,158.62) ; TP18.1 97.38,11.94 ; TP18.1 98.39,10.92 ; TP18.1 97.38,9.91 ; TP18.1 96.36,10.92 ; 46.58,159.64 45.69,159 v3(45.43,159) ; C18.2 78.45,155.32 v3(78.84,155.7) ; C123.2 v3(87.73,29.34) ; v3(22.19,160.91) 22.32,160.78 U1.2 ; C20.2 108.93,153.29 v3(109.32,153.29) ; C39.1 v3(114.78,140.46) ; CN7.26 v3(98.27,121.41) ; C98.2 46.82,39.5 ; C98.2 46.07,40.31 ; C98.2 46.07,38.68 ; R261.1 25.37,168.28 v3(25.34,168.3) ; v3(86.84,45.47) C143.1 v3(85.95,44.7) ; C119.2 v3(61.56,31.37) ; 125.7,105.92 v3(125.95,105.92) ; v3(125.95,105.92) 125.95,105.66 ; v3(125.95,105.92) 125.95,106.17 ; v3(125.95,105.92) 126.21,105.92 ; C66.1 v3(18.13,96.65) ; C103.2 v3(76.8,39.5) ; v3(29.56,115.32) 29.81,115.06 CN6.36 ; C36.1 v3(55.47,145.92) ; C45.2 76.3,126.62 76.8,126.11 v3(76.93,126.11) ; TP3.1 16.1,162.81 ; TP3.1 17.11,161.8 ; TP3.1 16.1,160.78 ; TP3.1 15.08,161.8 ; v3(54.45,156.84) C17.2 ; CN15.4 124.21,86.36 ; CN15.4 123.19,85.34 ; CN15.4 123.19,87.38 ; 34.29,170.23 CN1.8 ; CN1.8 35.25,171.44 ; CN1.8 33.34,171.44 ; CN15.10 123.19,79.76 ; CN15.10 124.21,78.74 ; CN15.10 123.19,77.72 ; U35.5 v3(93.97,15.14) ; C42.2 79.98,131.95 v3(80.87,131.95) ; U30.14 v3(70.96,21.08) ; C19.2 99.66,153.31 100.43,152.55 v3(100.43,152.35) ; C142.2 v3(13.68,11.13) ; R232.1 v3(75.66,20.32) ; 117.79,58.27 CN17.6 ; CN17.6 119.63,60.11 ; CN17.6 121.48,58.27 ; CN17.6 119.63,56.43 ; U36.2 10.22,13.19 v3(10.81,13.79) ; CN15.14 124.21,73.66 ; CN15.14 123.19,72.64 ; CN15.14 123.19,74.68 ; R220.2 118.59,29.36 ; R220.2 118.59,28.04 ; R220.2 v3(117.57,28.7) ; v3(88.18,145.81) 88.09,145.9 88.09,146.18 88.11,146.19 C31.2 ; C95.1 72.99,43.43 v3(73.63,43.43) ; T6.2 v3(92.99,35.62) ; C72.2 82.77,91.31 83.03,91.06 v3(83.66,91.06) ; v3(81.25,40.26) 80.87,39.88 R196.2 ; C97.2 v3(68.7,41.91) ; R251.1 v3(89,14.73) ; C52.1 78.96,111.38 v3(78.71,111.12) 78.2,111.63 C53.2 ; C24.1 2.25,151.92 ; C24.1 v3(1.37,151.26) ; C24.1 2.25,150.6 ; 22.19,69.32 C82.2 ; C82.2 22.19,70.38 ; C82.2 v3(21.05,69.85) ; 7.46,144.53 CN4.3 ; CN4.3 9.49,144.53 ; CN4.3 8.48,143.51 ; CN4.3 8.48,145.54 ; v3(75.15,45.21) 75.66,45.72 C145.2 ; 123.19,80.26 CN15.8 ; CN15.8 123.19,82.3 ; CN15.8 124.21,81.28 ; R163.1 v3(115.67,67.69) ; 15.21,117.7 R77.1 ; R77.1 v3(14.45,119.13) ; R77.1 15.21,119.02 ; C126.2 87.09,26.8 v3(87.85,27.56) ; v3(113.84,55.63) 113.58,55.88 R171.2 ; 57.75,46.61 v3(56.97,46.61) ; C118.2 v3(88.11,31.5) ; C33.2 v3(54.32,146.56) ; 100.35,27.06 CN19.30 ; CN19.30 102.18,27.06 ; CN19.30 101.26,27.97 ; v3(72.36,29.84) C122.2 ; C25.1 v3(14.83,150.11) ; C9.1 v3(50.51,158.24) ; R113.2 v3(9.24,97.41) ; C15.2 24.86,158.12 v3(24.86,157.35) ; 12.67,91.44 C71.2 ; C71.2 12.67,93.47 ; C71.2 11.78,92.46 ; C71.2 v3(13.85,92.46) ; v3(50.51,35.18) R202.1 ; CN18.6 v3(13.82,48.02) ; CN13.8 5.3,85.5 ; CN13.8 6.22,84.58 ; CN13.8 4.39,84.58 ; RV3.3 103.17,7.75 ; RV3.3 101.49,7.75 ; RV3.3 102.33,8.59 ; RV3.3 102.33,6.91 ; C101.2 45.56,38.43 ; C101.2 45.56,37.52 ; C101.2 46.02,37.97 ; C74.1 v3(64.48,91.19) ; CN6.39 24.63,112.52 v3(24.2,112.09) ; C60.1 v3(85.69,106.17) ; C32.2 v3(51.91,145.41) ; v3(69.56,43.69) 69.69,43.81 69.69,44.45 C94.1 ; C10.1 v3(58.26,161.93) ; R170.1 v3(70.25,56.39) ; JP4.1 15.97,139.45 ; JP4.1 13.94,139.45 ; JP4.1 14.95,140.46 ; JP4.1 14.95,138.43 ; 15.59,152.78 v3(14.57,152.78) ; v3(80.61,139.06) 80.61,138.81 C41.1 ; 57.75,51.18 v3(56.99,51.18) ; 57.75,48.01 v3(56.86,48.01) ; v3(110.05,128.17) 110.05,127.48 C44.2 ; C1.1 v3(42.89,167.13) ; CN15.16 124.21,71.12 ; CN15.16 123.19,70.1 ; CN15.16 123.19,72.14 ; R218.2 v3(68.8,33.27) ; 118.59,41.76 R191.2 ; R191.2 118.59,43.08 ; R191.2 v3(117.44,42.42) ; C109.2 v3(72.74,34.04) ; C38.1 67.66,140.84 v3(67.41,140.59) ; R226.1 v3(80.23,26.69) ; C26.1 v3(1.49,149.99) ; R19.2 v3(87.73,161.42) ; C99.2 38.63,37.72 ; C99.2 37.69,36.91 ; C99.2 36.75,37.72 ; C99.2 37.69,38.53 ; R124.2 v3(39.72,89.53) ; C108.2 v3(72.36,35.43) ; SB7.2 v3(123.62,139.06) ; C51.1 60.93,115.82 60.17,115.06 v1(60.17,114.55) ; CN17.4 117.86,53.47 ; CN17.4 116.97,52.58 ; CN17.4 116.97,54.36 ; R21.1 v3(19.91,159.51) ; R243.1 v3(76.93,15.75) ; v3(86.71,161.29) C11.2 ; R234.1 v3(51.66,19.56) ; 18.64,50.16 v3(19.53,50.16) ; R203.2 v3(40.23,36.7) ; C61.1 v3(102.71,105.99) ; R121.1 v3(100.43,92.76) ; C56.2 C57.2 59.15,108.2 58.54,107.59 v3(58.41,107.59) ; C139.2 v3(99.41,13.87) ; 28.42,31.62 v3(28.42,30.73) ; B1.1 v3(50.32,5.02) ; B1.1 48.94,4.25 ; B1.1 47.92,5.02 ; B1.1 48.94,5.78 ; 6.98,35.41 L2.4 5.74,34.16 ; v3(17.49,123.32) 18,122.81 U8.2 ; C125.1 v3(73.37,26.04) ; R192.1 v3(121.25,42.42) ; CN12.5 v3(101.44,84.96) ; C68.1 v3(8.35,94.87) ; R155.1 v3(114.01,79.25) ; C117.1 v3(69.82,33.27) ; C86.1 v3(60.67,56.39) ; 74.14,61.09 73.76,61.09 v3(73.25,61.59) ; C144.2 v3(39.72,90.55) ; R245.2 74.92,13.84 ; R245.2 v3(74.39,14.73) ; R245.2 73.86,13.84 ; 92.93,1.02 v3(92.93,1.27) ; v3(92.93,1.27) 92.93,1.52 ; v3(92.93,1.27) 92.68,1.27 ; v3(92.93,1.27) 93.19,1.27 ; v3(92.75,135.94) 93.47,136.65 CN7.1 ; R240.2 v3(51.66,15.88) ; C29.2 v3(4.54,146.81) ; v3(38.53,64.97) BT1.2 v3(34.16,64.97) ; v3(56.1,16.51) 56.48,16.13 R241.2 ; C48.1 v3(46.83,118.36) ; CN7.15 v3(96.87,127.76) ; C34.1 v3(56.74,146.43) ; 112.31,116.84 v3(112.31,117.02) ; v3(112.31,117.02) 112.16,117.02 ; v3(112.31,117.02) 112.49,117.02 ; C96.2 67.79,43.69 v3(67.91,43.81) 67.66,44.07 R187.2 ; C12.2 v3(89.63,161.42) ; C78.1 4.44,87.5 ; C78.1 3.91,88.04 ; C78.1 3.91,86.97 ; C75.2 41.12,86.49 v3(40.99,86.49) ; C54.2 v3(64.99,107.31) ; C112.2 v3(61.94,33.66) ; v3(19.02,71.63) C80.2 20.67,72.26 U20.2 ; C132.2 v3(75.66,21.34) ; 117.32,130.68 117.32,131.7 ; 117.32,131.7 116.3,131.7 ; 117.32,131.7 118.33,131.7 ; U30.4 v3(58.26,17.65) ; C69.1 v3(18.13,93.09) ; 80.11,118.49 80.11,118.11 79.85,117.86 v3(79.85,117.6) ; v3(106.01,140.51) 106.01,139.95 C40.2 ; C43.1 50.13,132.72 v3(49.63,133.22) ; C104.2 v3(78.07,39.5) ; L3.2 v3(90.52,32.26) ; v3(85.69,109.73) 85.57,109.6 C59.2 85.57,107.06 v3(85.69,106.93) ; U30.22 v3(62.07,30.23) ; 32.42,169.31 CN1.7 33.21,168.26 ; v3(78.84,72.52) 78.45,72.9 C79.2 ; 103.35,77.34 v3(101.44,77.34) ; CN18.9 v3(13.8,44.67) ; R137.2 63.72,85.6 v3(64.36,85.6) ; CN12.3 v3(101.44,86.23) ; R230.1 v3(78.45,22.86) ; C49.1 v3(18.38,118.75) ; R168.2 v3(63.72,57.28) ; C110.2 v3(88.11,34.04) ; C137.2 v3(64.36,16.13) ; 57.75,52.45 v3(56.86,52.45) ; CN12.9 v3(101.44,82.42) ; C37.1 v3(65.93,145.67) ; C30.2 v3(93.82,148.87) ; C141.1 v3(57.12,13.84) ; C3.2 v3(46.07,163.32) ; C58.1 76.93,108.84 76.68,108.58 v3(76.42,108.58) ; C121.2 v3(87.73,30.35) ; CN6.11 v3(28.16,130.3) ; CN12.13 v3(101.44,79.88) ; LD8.1 v3(18.01,2.54) ; R206.2 v3(50.51,33.27) ; CN12.15 v3(101.44,78.61) ; 57.75,54.99 v3(56.86,54.99) ; CN6.22 v3(29.69,123.95) ; C28.2 v3(23.84,148.08) ; v3(62.58,16.89) 61.94,16.89 C135.2 ; R139.2 v3(92.04,82.8) ; C120.2 v3(72.36,31.24) ; v3(47.72,162.18) C6.1 ; R267.2 v3(88.87,38.73) ; C35.1 v3(61.69,145.8) ; R164.1 v3(115.67,65.41) ; U36.5 v3(8.17,12.6) ; R184.2 v3(86.84,43.81) ; CN3.7 v3(113.63,145.29)
  BOTTOM w0.508: RV1.2 33.45,5.21 ; RV1.2 31.77,5.21 ; RV1.2 32.61,4.37 ; RV1.2 32.61,6.05 ; CN15.4 124.21,86.36 ; CN15.4 122.17,86.36 ; CN15.4 123.19,85.34 ; CN15.4 123.19,87.38 ; 11.65,148.84 v3(11.65,149.1) ; v3(11.65,149.1) 11.4,149.1 ; v3(11.65,149.1) 11.65,149.35 ; v3(11.65,149.1) 11.91,149.1 ; CN9.5 118.08,117.17 ; CN9.5 116.81,118.31 ; CN9.5 116.81,116.03 ; CN23.5 73.63,4.96 ; CN23.5 74.53,3.96 ; CN23.5 72.73,3.96 ; CN23.5 v3(73.63,2.54) ; 123.19,65.02 CN15.20 ; CN15.20 122.17,66.04 ; CN15.20 124.21,66.04 ; CN15.20 123.19,67.06 ; 38.37,146.18 SW1.3 ; SW1.3 40.3,146.18 ; SW1.3 39.34,147.14 ; SW1.3 39.34,145.21 ; CN15.16 123.19,72.14 ; CN15.16 124.21,71.12 ; CN15.16 122.17,71.12 ; CN15.16 123.19,70.1 ; 30.07,7.75 30.91,7.75 ; 30.07,7.75 29.23,7.75 ; 30.07,7.75 30.07,8.59 ; 30.07,7.75 30.07,6.91 ; L2.5 3.23,34.16 ; L2.5 1.99,32.92 ; L2.5 1.99,35.41 ; v3(31.44,167.39) 31.44,167.64 ; v3(31.44,167.39) 31.44,167.13 ; v3(31.44,167.39) 31.72,167.39 ; v3(31.44,167.39) 31.21,167.39 ; CN5.11 8.76,140.16 ; CN5.11 10.16,137.62 ; CN5.11 7.37,137.62 ; CN5.11 8.76,135.08 ; CN13.8 5.3,85.5 ; CN13.8 6.22,84.58 ; CN13.8 4.39,84.58 ; CN13.8 5.3,83.67 ; 122.17,73.66 CN15.14 ; CN15.14 124.21,73.66 ; CN15.14 123.19,72.64 ; CN15.14 123.19,74.68 ; 125.95,105.66 v3(125.95,105.92) ; v3(125.95,105.92) 126.21,105.92 ; v3(125.95,105.92) 125.7,105.92 ; v3(125.95,105.92) 125.95,106.17 ; 9.49,35.42 L2.6 ; L2.6 8.24,36.66 ; L2.6 9.49,37.91 ; L2.6 10.73,36.66 ; CN15.12 124.21,76.2 ; CN15.12 122.17,76.2 ; CN15.12 123.19,77.22 ; CN15.12 123.19,75.18 ; v3(23.84,148.08) 23.84,148.34 ; v3(23.84,148.08) 23.84,147.83 ; v3(23.84,148.08) 24.1,148.08 ; v3(23.84,148.08) 23.59,148.08 ; 118.21,96.57 CN9.11 ; CN9.11 118.21,101.65 ; CN9.11 119.6,99.11 ; CN9.11 116.81,99.11 ; 31.63,168.26 CN1.7 ; CN1.7 33.21,168.26 ; CN1.7 32.42,167.21 ; CN1.7 32.42,169.31 ; 28.42,30.48 v3(28.42,30.73) ; v3(28.42,30.73) 28.42,30.99 ; v3(28.42,30.73) 28.16,30.73 ; v3(28.42,30.73) 28.67,30.73 ; CN1.6 28.66,168.26 ; CN1.6 27.08,168.26 ; CN1.6 27.87,169.31 ; 25.34,168.15 v3(25.34,168.3) ; v3(25.34,168.3) 25.62,168.3 ; v3(25.34,168.3) 25.34,168.66 ; v3(25.34,168.3) 25.11,168.3 ; 92.68,1.27 v3(92.93,1.27) ; v3(92.93,1.27) 92.93,1.52 ; v3(92.93,1.27) 92.93,1.02 ; v3(92.93,1.27) 93.19,1.27 ; 75.15,165.35 CN2.16 76.17,166.37 ; CN17.4 116.97,54.36 ; CN17.4 116.97,52.58 ; CN17.4 117.86,53.47 ; CN17.4 116.08,53.47 ; CN5.10 10.16,112.57 ; CN5.10 8.76,115.11 ; CN5.10 7.37,112.57 ; CN5.10 8.76,110.03 ; 5.74,34.16 L2.4 ; L2.4 6.98,35.41 ; L2.4 8.23,34.16 ; L2.4 6.98,32.92 ; TP3.1 16.1,162.81 ; TP3.1 16.1,160.78 ; TP3.1 15.08,161.8 ; TP3.1 17.11,161.8 ; 18.89,145.85 R30.1 ; R30.1 19.6,146.56 ; R30.1 18.18,146.56 ; 122.17,83.82 CN15.6 ; CN15.6 123.19,84.84 ; CN15.6 123.19,82.8 ; CN15.6 124.21,83.82 ; v3(113.84,55.63) 113.84,55.88 ; v3(113.84,55.63) 113.84,55.37 ; v3(113.84,55.63) 113.54,55.63 ; v3(113.84,55.63) 114.01,55.63 ; CN4.3 9.49,144.53 ; CN4.3 7.46,144.53 ; CN4.3 8.48,145.54 ; CN4.3 8.48,143.51 ; 102.33,6.91 RV3.3 ; RV3.3 103.17,7.75 ; RV3.3 101.49,7.75 ; RV3.3 102.33,8.59 ; v3(125.95,63.25) 125.95,63.5 ; v3(125.95,63.25) 126.21,63.25 ; v3(125.95,63.25) 125.7,63.25 ; v3(125.95,63.25) 125.95,62.99 ; CN17.5 119.63,47.92 ; CN17.5 121.48,46.08 ; CN17.5 119.63,44.23 ; CN17.5 117.79,46.08 ; 46.7,37.59 v3(46.7,37.85) ; v3(46.7,37.85) 46.96,37.85 ; v3(46.7,37.85) 46.45,37.85 ; v3(46.7,37.85) 46.7,38.1 ; 7.37,128.12 CN5.6 ; CN5.6 7.37,130.4 ; CN5.6 8.64,129.26 ; CN5.6 6.1,129.26 ; 41.12,171.2 v3(41.12,171.45) ; v3(41.12,171.45) 40.86,171.45 ; v3(41.12,171.45) 41.12,171.7 ; v3(41.12,171.45) 41.37,171.45 ; v3(1.49,13.46) 1.75,13.46 ; v3(1.49,13.46) 1.49,13.72 ; v3(1.49,13.46) 1.49,13.21 ; v3(1.49,13.46) 1.24,13.46 ; 96.36,10.92 TP18.1 ; TP18.1 97.38,9.91 ; TP18.1 98.39,10.92 ; CN15.18 123.19,69.6 ; CN15.18 124.21,68.58 ; CN15.18 123.19,67.56 ; CN15.18 122.17,68.58 ; 72.1,165.35 CN2.20 71.09,166.37 ; CN17.6 121.48,58.27 ; CN17.6 119.63,56.43 ; CN17.6 117.79,58.27 ; CN17.6 119.63,60.11 ; 31.87,142.75 v3(31.87,142.93) ; v3(31.87,142.93) 31.87,143.26 ; v3(31.87,142.93) 31.72,142.93 ; v3(31.87,142.93) 32.23,142.93 ; CN9.10 119.6,124.16 ; CN9.10 118.21,126.7 ; CN9.10 118.21,121.61 ; CN9.10 116.81,124.16 ; 14.95,138.43 JP4.1 ; JP4.1 13.94,139.45 ; JP4.1 15.97,139.45 ; JP4.1 14.95,140.46 ; 122.17,81.28 CN15.8 ; CN15.8 123.19,82.3 ; CN15.8 124.21,81.28 ; CN15.8 123.19,80.26 ; CN1.9 26.95,171.44 ; CN1.9 25.04,171.44 ; CN1.9 25.99,170.23 ; 24.29,168.15 v3(24.29,168.46) ; v3(24.29,168.46) 24.1,168.46 ; v3(24.29,168.46) 24.61,168.46 ; v3(24.29,168.46) 24.29,168.66 ; 122.17,78.74 CN15.10 ; CN15.10 123.19,79.76 ; CN15.10 124.21,78.74 ; CN15.10 123.19,77.72 ; CN2.18 74.64,165.35 ; CN2.18 72.61,165.35 ; CN2.18 73.63,166.37 ; 10.16,123.95 CN5.3 ; CN5.3 10.16,126.24 ; CN5.3 11.43,125.09 ; CN5.3 8.89,125.09 ; v3(125.95,13.97) 125.95,14.22 ; v3(125.95,13.97) 125.7,13.97 ; v3(125.95,13.97) 125.95,13.72 ; v3(125.95,13.97) 126.21,13.97 ; CN1.8 35.25,171.44 ; CN1.8 33.34,171.44 ; CN1.8 34.29,170.23 ; CN23.17 v3(60.93,23.62)
  vias: v3(1.24,171.45) v3(1.24,163.83) v3(1.24,156.72) v3(1.24,143.76) v3(1.24,137.41) v3(1.24,126.24) v3(1.24,111.25) v3(1.24,99.06) v3(1.24,70.1) v3(1.49,41.15) v3(1.49,27.94) v3(1.49,1.52) v3(2.25,56.39) v3(6.57,152.53) v3(6.57,150.75) v3(7.46,151.64) v3(8.48,152.53) v3(8.48,150.75) v3(8.48,78.74) v3(10.89,11.35) v3(12.62,12.65) v3(19.65,152.65) v3(19.65,150.62) v3(20.67,151.64) v3(21.69,152.65) v3(21.69,150.62) v3(23.08,42.37) v3(23.08,41.5) v3(24.02,41.55) v3(24.07,42.34) v3(24.61,1.52) v3(26.58,140.74) v3(28.15,162.91) v3(31.46,163.18) v3(36.93,35.94) v3(37.69,35.94) v3(38.45,35.94) v3(38.58,1.52) v3(45.56,36.07) v3(45.56,34.29) v3(46.58,36.07) v3(46.58,34.29) v3(46.58,18.54) v3(46.58,16.76) v3(47.47,39.88) v3(47.47,38.99) v3(47.59,18.54) v3(47.59,16.76) v3(47.72,20.32) v3(48.48,22.35) v3(48.48,21.46) v3(54.71,104.65) v3(56.74,104.65) v3(58.39,104.65) v3(58.39,1.52) v3(59.15,171.7) v3(68.04,106.17) v3(68.04,105.03) v3(69.95,35.31) v3(69.95,34.42) v3(70.71,35.31) v3(70.71,34.42) v3(71.54,52.26) v3(76.93,1.27) v3(80.61,20.57) v3(80.61,18.67) v3(82.52,20.57) v3(82.52,18.67) v3(96.62,16.38) v3(96.62,13.89) v3(98.34,15.14) v3(104.36,1.27) v3(108.93,51.31) v3(108.93,49.78) v3(113,1.27) v3(125.7,92.96) v3(125.7,80.52) v3(125.7,54.36) v3(125.7,44.2) v3(125.7,1.52) v3(125.95,153.42) v3(125.95,141.73) v3(125.95,129.03) v3(125.95,117.86) v3(125.95,29.97)
VDD: length 200.7
  TOP w0.229: v2(81.98,31.24) U29.D2
  TOP w0.254: U22.31 79.68,72.46 79.47,72.67 C79.1 ; U33.21 79.22,19.81 77.69,21.34 C132.1 ; v3(65.12,64.92) 64.39,64.2 U21.24 ; C97.1 66.38,41.91 66.14,41.67 U25.5 ; U4.1 17.28,152.61 C21.1 ; v3(24.23,93.98) 23.96,94.25 U12.1 ; C92.1 71.85,49.15 71.61,48.91 U24.8 ; U25.1 v3(63.46,43.17) ; U22.42 v3(74.18,70.03) ; C22.1 3.82,152.61 U3.1
  TOP w0.279: U21.25 v3(64.39,69.76) ; v3(55.34,69.6) 55.34,69.72 55.89,70.27 U21.42 ; U21.1 52.89,62.01 53.05,61.85 C83.1 ; C31.1 87.09,147.83 86.07,148.84 86.07,149.97 85.94,150.11 U2.E1 ; C66.2 19.16,95.75 U12.5 ; v4(85.06,155.19) 85.19,155.06 U2.D6 ; 86.71,19.94 86.71,19.93 U32.6 ; U2.A6 82.66,154.81 82.01,154.81 ; U21.31 v3(61.39,69.76) ; U32.14 v3(92.68,19.44)
  TOP w0.305: U6.8 117.36,139.02 116.81,139.57 C39.2 ; U5.D8 101.45,150.11 101.01,150.55 101.01,152.81 100.68,153.14 C19.1 ; U14.16 81.62,91.3
  TOP w0.356: C76.1 65.64,86.47 U16.5 ; U13.5 65.64,90.16 C74.2 ; U15.5 42.78,88 v3(42.67,87.88)
  TOP w0.381: U5.F1 103.45,142.9 103.47,142.88 103.47,141.73
  TOP w0.508: v3(80.31,73.3) 80,73.3 79.98,73.28 C79.1 ; C21.1 16.17,153.72 v3(16.17,153.8) ; R200.2 v3(84.17,38.73) ; v3(76.8,154.31) C18.1 78.45,154.31 78.96,154.81 82.01,154.81 ; C121.1 85.82,31.24 C118.1 84.8,31.5 v3(84.68,31.37) ; v3(84.8,72.77) 84.3,73.28 R161.1 ; v3(98.27,111.84) 98.29,111.84 98.98,112.52 CN7.40 ; R264.1 121.63,136.91 v3(121.63,136.7) 121.63,136.5 121.15,136.02 R263.1 ; CN12.1 v3(101.44,87.5) ; v3(88.87,160.02) 89.38,159.51 C12.1 ; CN3.5 116.17,144.96 115.94,145.19 v3(115.92,145.19) ; R46.2 20.03,135.79 v3(20.01,135.76) ; v3(77.06,22.1) 77.57,21.59 C132.1 ; 18.64,52.45 v3(19.53,52.45) ; 77.69,156.59 78.33,156.59 v3(78.71,156.97) ; 18.64,51.31 v3(19.53,51.31) ; C39.2 v3(117.7,140.46) ; B2.1 v3(65.45,6.73) ; v3(18.33,119.76) C49.2 19.27,119.89 U8.3 ; v3(70.96,49.78) 71.72,49.78 C92.1 ; R41.1 109.47,140.46 v3(109.39,140.54) ; R117.2 26.08,94.49 v1(26.59,93.98) ; R190.1 v3(59.79,43.05) ; v3(82.14,90.55) 82.65,90.04 R127.1 ; C22.1 v3(3.78,153.8) ; 63.34,28.8 63.34,31.24 C119.1 C112.1 v3(63.47,33.78) ; R133.1 v3(96.74,87.63) ; R120.2 101.82,92.46 v3(101.19,93.09) ; v3(19.53,49.4) 18.26,49.4 17.88,49.78 17.88,49.91 C90.1 17.57,50.22 CN18.4 ; R193.1 v3(59.79,41.91) ; R74.1 105.76,121.79 v3(106.65,122.68) ; v1(102.71,140.87) 103.07,140.87 104.36,139.57 C40.1 104.62,140.59 103.47,141.73 ; B2.4 v3(74.45,6.76) ; R57.2 43.78,129.41 v3(43.53,129.67) ; 86.71,19.94 v3(86.71,19.18) ; R29.1 v3(22.32,145.92) ; R248.2 v3(84.17,14.73) ; R197.1 v3(87.98,37.85) ; C97.1 66.77,41.66 67.28,41.15 72.1,41.15 v3(72.61,41.66) ; R157.2 v3(114.07,77.72) ; v3(105,153.03) 105,153.37 105.12,153.49 R25.1 ; 18.64,47.12 v3(19.53,47.12) ; U9.8 C44.1 108.93,127.89 v3(109.32,128.27) ; C66.2 v3(19.15,96.65) ; R152.2 v3(113.89,82.8) ; R249.2 v3(86.07,14.73) ; R28.1 92.81,148.69 v3(93.03,148.92) ; C74.2 v3(64.48,90.17) ; R237.1 v3(75.28,17.91) ; v3(87.34,145.72) 87.29,145.72 87.09,145.92 C31.1 ; v3(23.97,97.28) 24.28,97.28 24.53,97.03 R114.2 ; R231.1 v3(84.55,22.86) ; v3(123.03,140.46) R42.1 ; R32.1 92.42,144.65 v3(92.02,144.65) ; C76.1 v3(64.48,86.49) ; 70.71,61.09 v3(69.95,61.09) ; R126.2 114.24,90.7 v3(114.24,90.96) ; v3(100.88,154.56) 100.88,153.87 C19.1 ; v3(56.1,88.01) R135.2 57.63,88.01 57.81,88.2 T3.4 ; R160.2 v3(113.96,74.42) ; R153.2 v3(114.01,81.03) ; C72.1 81.62,91.3 81.62,91.1 81.1,90.58 v3(81.1,90.53) ; R247.2 v3(82.52,14.73) ; R60.2 43.78,126.87 v3(44.16,126.49) ; R229.1 92.7,22.99 v3(92.91,22.78) ; R233.1 v3(75.28,19.18) ; R250.2 v3(87.73,14.73) ; C83.1 52.29,61.59 v3(51.53,62.36) ; 18.64,53.59 v3(19.53,53.59) ; R246.1 v3(81.12,14.73) ; v3(68.29,108.08) R96.2 ; 18.64,45.97 v3(19.53,45.97) ; R51.2 v3(122.9,134.24) ; 57.75,45.59 v3(56.86,45.59)
  BOTTOM w0.381: v3(84.68,31.37) 84.17,31.88 82.62,31.88 v2(81.98,31.24)
  BOTTOM w0.508: v3(22.32,145.92) 21.46,145.06 16.94,145.06 15.72,146.28 15.72,152.4 16.17,152.86 v3(16.17,153.8) 15.79,154.18 13.99,154.18 9.75,149.94 5.89,149.94 3.78,152.04 v3(3.78,153.8) ; v3(51.53,62.36) 51.53,66.04 55.09,69.6 v3(55.34,69.6)
